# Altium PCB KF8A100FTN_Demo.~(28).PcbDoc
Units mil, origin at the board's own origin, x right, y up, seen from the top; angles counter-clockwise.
Board outline 6000 x 4000 mil, 2 copper layers (Top Layer, Bottom Layer); 25 components, 35 nets, 113 pads, 0 vias.
Unrouted connection lines stored in the file: 71.
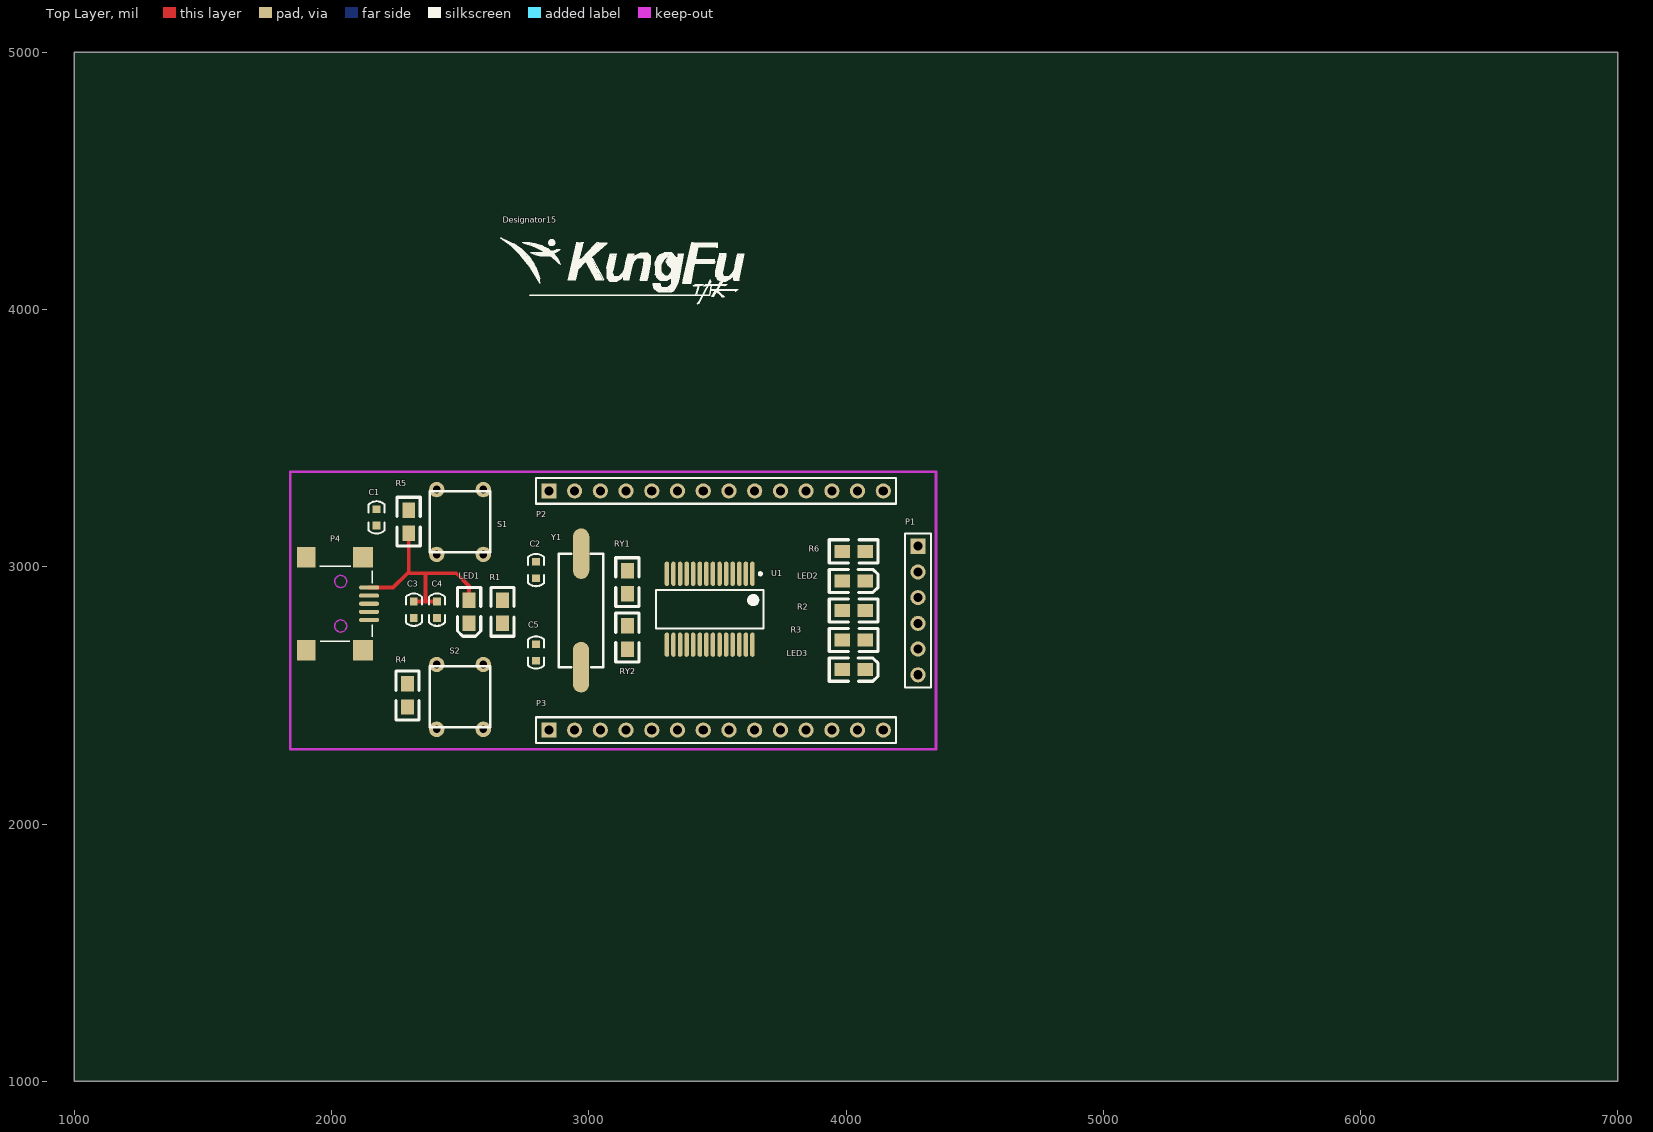
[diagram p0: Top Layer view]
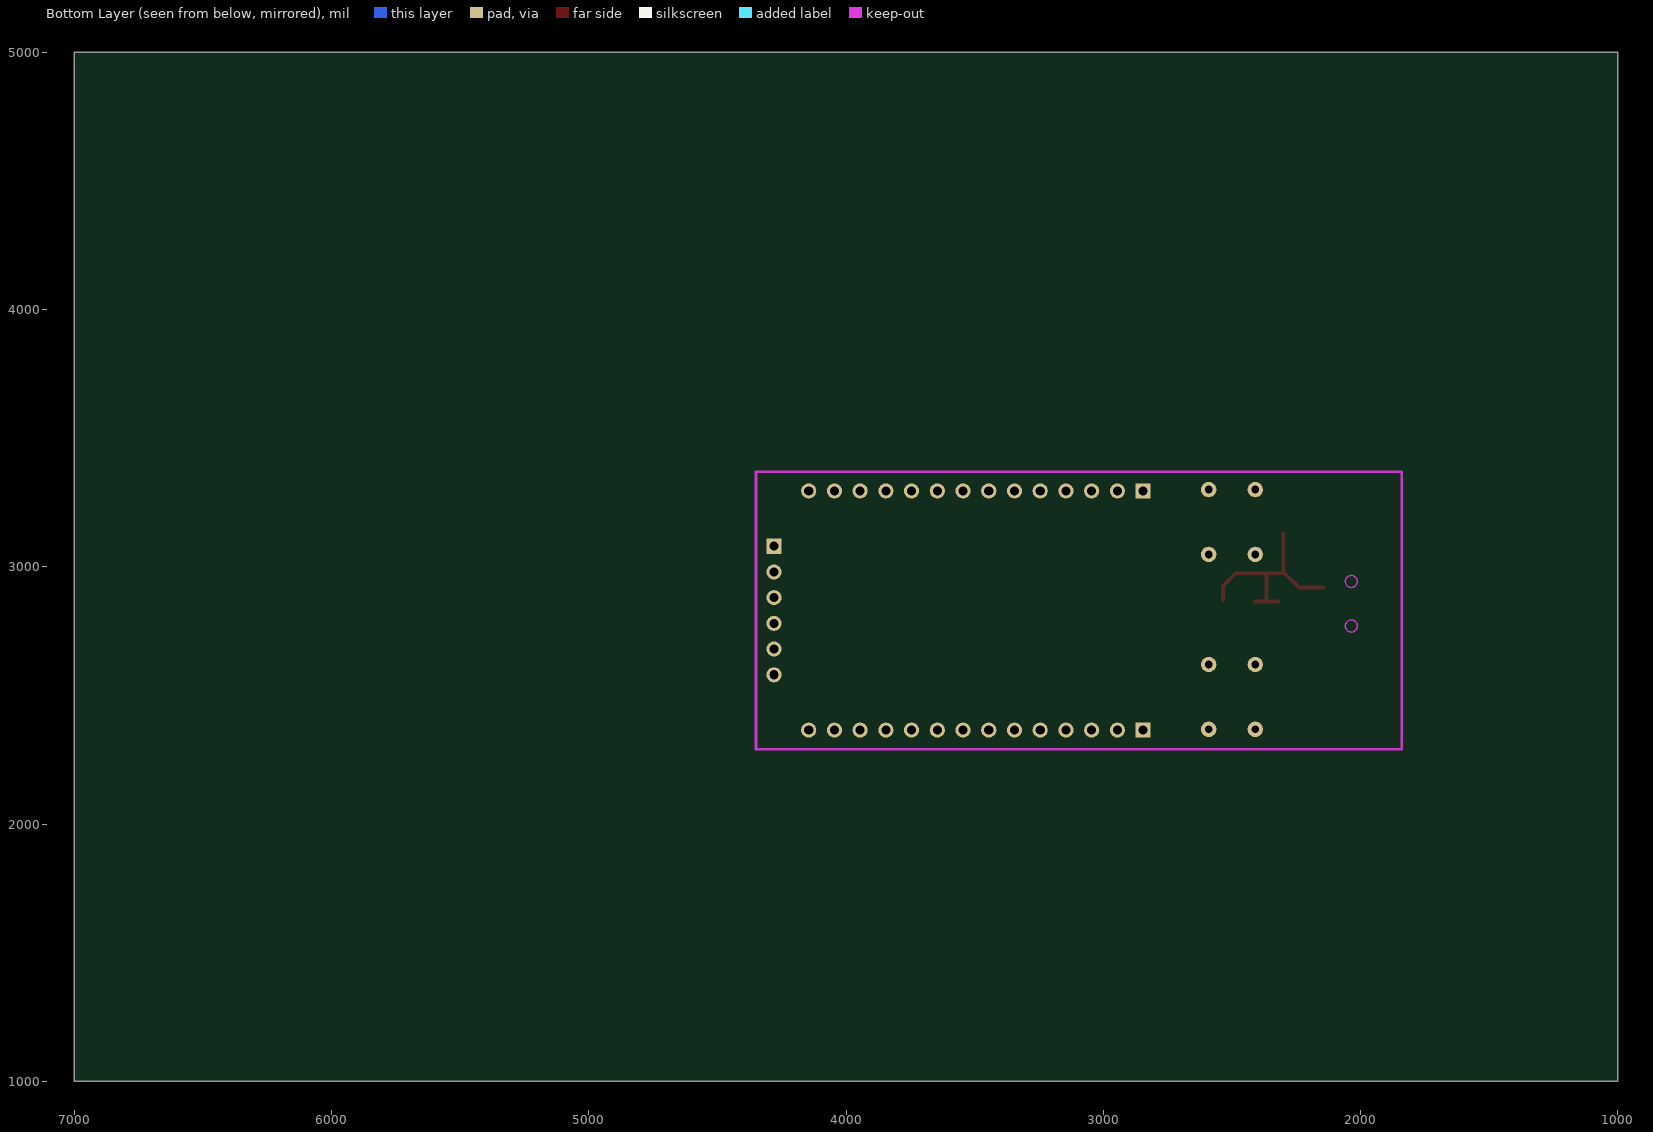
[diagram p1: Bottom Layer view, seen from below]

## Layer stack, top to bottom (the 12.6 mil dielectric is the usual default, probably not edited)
Top Solder: solder mask 0.4, Solder Resist, Dk 3.5
Top Layer: signal copper 1.4
Dielectric 1: dielectric 12.6, FR-4, Dk 4.8
Bottom Layer: signal copper 1.4
Bottom Solder: solder mask 0.4, Solder Resist, Dk 3.5

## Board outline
1000,1000 7000,1000 7000,5000 1000,5000

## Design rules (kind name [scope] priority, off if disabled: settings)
Clearance [All] p1: gap=7
PolygonConnect [All] p1: connectstyle=Relief reliefconductorwidth=10 reliefentries=4 polygonreliefangle="90 Angle" airgapwidth=10
RoutingVias [All] p1: holewidth=28 width=50 viastyle="Through Hole" minholewidth=28 minwidth=50 maxholewidth=28 maxwidth=50
SolderMaskExpansion [All] p1: expansion=4
UnpouredPolygon [All] p1: allowunpoured=FALSE
Width [All] p1: maxlimit=30 minlimit=10 preferedwidth=15
29 further rules are at their usual default settings.

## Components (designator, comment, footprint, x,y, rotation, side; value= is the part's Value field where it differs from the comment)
C1 "Comment" 0603C 2175,3160 r90 top
C2 "Comment" 0603C 2795,2955 r90 top
C3 "Comment" 0603C 2320,2865 r270 top
C4 "Comment" 0603C 2410,2865 r270 top
C5 "Comment" 0603C 2795,2635 r90 top
Designator15 "Comment" LOGO 2770,4055 r0 top
LED1 "Comment" D0805 2535,2870 r270 top
LED2 "Comment" D0805 3984.89,2945 r0 top
LED3 "Comment" D0805 3984.89,2600 r0 top
P1 "Comment" HDR1X6 4280,3080 r270 top
P2 "Comment" HDR1X14 2845,3295 r0 top
P3 "Comment" HDR1X14 2845,2365 r0 top
P4 "Comment" USB_MINI_B 2030,2890 r0 top
R1 "Comment" 0805 2665,2780 r90 top
R2 "Comment" 0805 3985,2830 r0 top
R3 "Comment" 0805 3985,2715 r0 top
R4 "Comment" 0805 2295,2455 r90 top
R5 "Comment" 0805 2300,3220 r270 top
R6 "Comment" 0805 3985,3060 r0 top
RY1 "Comment" 0805 3150,2985 r270 top
RY2 "Comment" 0805 3150,2770 r270 top
S1 "Comment" KEY6*6 2590,3300 r270 top
S2 "Comment" KEY6*6 2590,2620 r270 top
U1 "Comment" SSOP-SS28_M 3470,2835 r270 top
Y1 "Comment" CRYSTAL 2970,2610 r90 top

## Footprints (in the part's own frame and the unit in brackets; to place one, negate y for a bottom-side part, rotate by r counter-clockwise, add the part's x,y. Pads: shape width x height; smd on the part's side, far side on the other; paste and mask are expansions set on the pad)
0603C [mil]
  rect 30x30 smd: 1(0,0) 2(64,0)
  silkscreen extent -31,-31 95,31
0805 [mil]
  rect 60x50 smd: 1(-0.11,0) 2(89.89,0)
  silkscreen extent -50,-45 140,45
CRYSTAL [mm]
  oval 5x1.6 smd: 1(0,0) 2(11.2,-0.01)
  silkscreen extent 0,-2.2 11.2,2.2
D0805 [mil]
  rect 60x50 smd: 1(0,0) 2(90,0)
  silkscreen extent -50,-45 140,45
HDR1X6 [mm] "Connector; Header; 6 Position"
  rect 1.5x1.5 hole 0.9: 1(0,0)
  round 1.5 hole 0.9: 2(2.54,0) 3(5.08,0) 4(7.62,0) 5(10.16,0) 6(12.7,0)
  silkscreen extent -1.27,-1.27 13.97,1.27
HDR1X14 [mm] "Connector; Header; 14 Position"
  rect 1.5x1.5 hole 0.9: 1(0,0)
  round 1.5 hole 0.9: 2(2.54,0) 3(5.08,0) 4(7.62,0) 5(10.16,0) 6(12.7,0) 7(15.24,0) 8(17.78,0) 9(20.32,0) 10(22.86,0) 11(25.4,0) 12(27.94,0) 13(30.48,0) 14(33.02,0)
  silkscreen extent -1.27,-1.27 34.29,1.27
KEY6*6 [mil]
  round 60 hole 30: 1(0,0) 2(0,-181.1) 3(251.97,0) 4(251.97,-181.1)
  silkscreen extent 7,-209 243,28
LOGO [mil]
  silkscreen extent -114,-33 835,225
SSOP-SS28_M [mm] "SOP, 28-Leads, Body 10.2x5.2mm, Pitch 0.65mm, IPC Low Density"
  oval 2.4x0.45 smd: 1(-3.5,4.225) 2(-3.5,3.575) 3(-3.5,2.925) 4(-3.5,2.275) 5(-3.5,1.625) 6(-3.5,0.975) 7(-3.5,0.325) 8(-3.5,-0.325) 9(-3.5,-0.975) 10(-3.5,-1.625) 11(-3.5,-2.275) 12(-3.5,-2.925) 13(-3.5,-3.575) 14(-3.5,-4.225) 15(3.5,-4.225) 16(3.5,-3.575) 17(3.5,-2.925) 18(3.5,-2.275) 19(3.5,-1.625) 20(3.5,-0.975) 21(3.5,-0.325) 22(3.5,0.325) 23(3.5,0.975) 24(3.5,1.625) 25(3.5,2.275) 26(3.5,2.925) 27(3.5,3.575) 28(3.5,4.225)
  silkscreen extent -3.62,-5.3 1.9,5.3, body extent -2.7,-5.3 2.7,5.3, height 2
USB_MINI_B [mm] "USB_MINI_B"
  oval 2x0.4 smd: 1(2.941,0.744) 2(2.941,-0.056) 3(2.941,-0.856) 4(2.941,-1.656) 5(2.941,-2.456)
  rect 1.797x2 smd: 6(-3.259,-5.456) 6(-3.259,3.744)
  rect 2x2 smd: 6(2.341,-5.456) 6(2.341,3.744)
  Keep-Out Layer circle w0.127: c0.141,1.344 r0.6
  Keep-Out Layer circle w0.127: c0.141,-3.056 r0.6
  silkscreen extent -1.93,-4.58 3.24,2.85

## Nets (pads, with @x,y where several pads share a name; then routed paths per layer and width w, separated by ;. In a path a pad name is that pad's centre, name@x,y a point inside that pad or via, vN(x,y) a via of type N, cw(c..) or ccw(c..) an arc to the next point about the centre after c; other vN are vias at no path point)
L1: LED1.2 R1.1
L2: LED2.2 R2.1
L3: LED3.2 R3.1
P04: P2.13 RY2.1 U1.2
P05: P2.12 RY1.2 U1.3
P10: P3.4 U1.18
P11: P3.3 U1.17
P12: P3.2 U1.16
P13: P3.1 U1.15
P14: P2.1 U1.14
P15: P2.2 U1.13
P16: P2.3 U1.12
P17: P2.4 U1.11
P20: P2.11 U1.4
P21: P2.10 U1.5
P22: P2.9 U1.6
P23: P2.8 U1.7
P24: P2.7 U1.8
P25: P2.6 U1.9
P26: P2.5 R4.2 S2.2 S2.4 U1.10
P30: LED3.1 P3.12 U1.26
P31: LED2.1 P3.11 U1.25
P32: P3.10 U1.24
P33: P3.9 U1.23
P34: P3.8 U1.22
P35: P3.7 U1.21
RST: P1.1 P2.14 R6.2 U1.1
S2: C1.2 R5.1 R6.1 S1.2 S1.4
S2-1: 
SPCLK: P1.5 P3.13 U1.27
SPDAT: P1.4 P3.14 U1.28
VDD: C3.1 C4.1 LED1.1 P1.2 P3.6 P4.1 R4.1 R5.2 U1.20 | length 845.2
  Top Layer w15: P4.1 2239.28,2919.28 2295,2975 ; R5.2 2300,2980 2295,2975 ; C3.1 2365,2865 ; C4.1 2365,2865 ; LED1.1 2535,2925 2485,2975 2365,2975 ; 2295,2975 2365,2975 ; 2365,2865 2365,2975
VSS: C1.1 C2.1 C3.2 C4.2 C5.2 P1.3 P3.5 P4.5 P4.6 R1.2 R2.2 R3.2 S1.1 S1.3 S2.1 S2.3 U1.19
Y1: C5.1 RY2.2 Y1.1
Y2: C2.2 RY1.1 Y1.2
pads on no net: P1.6 P4.2 P4.3 P4.4

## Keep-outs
Keep-Out Layer:
  lines w10: 1840,2290 4350,2290 4350,3370 1840,3370 1840,2290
